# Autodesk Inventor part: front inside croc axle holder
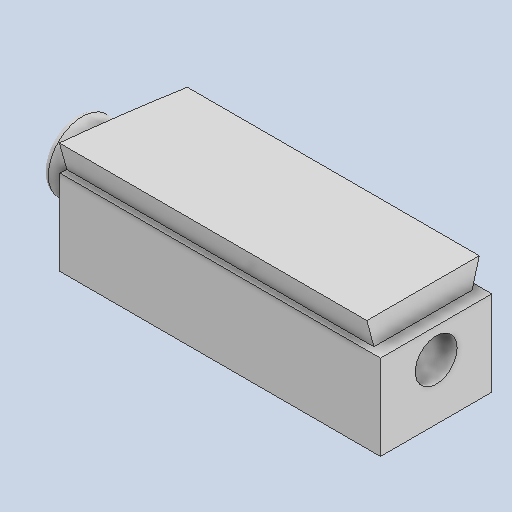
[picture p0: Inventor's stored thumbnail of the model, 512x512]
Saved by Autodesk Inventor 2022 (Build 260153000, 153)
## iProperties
Created: 2021-07
Part Number: front inside croc axle holder
Material: Generic
Document SubType Name: Modeling
Designer: garre
Density: 1 g/cm^3
Appearance: Default
Author: garre
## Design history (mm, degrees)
derived "croc skate axle holders.ipt"
feature "front inside::croc skate axle holders.ipt" dims "d0" = 10
tag "TaggingFeature1"
body "Solid1"
